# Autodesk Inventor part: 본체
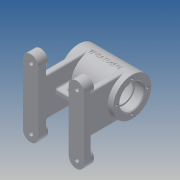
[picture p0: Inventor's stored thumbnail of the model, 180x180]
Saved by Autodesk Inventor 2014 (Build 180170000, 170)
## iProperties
Created: 2015-11
Part Number: 본체
Material: 일반
Document SubType Name: Modeling
Designer: Owner
Density: 1 g/cm^3
Appearance: 기본값
Author: Owner
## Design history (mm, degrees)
sketch "스케치1"
  geometry: L1 (0, 0)-(0, 25); L2 (0, 25)-(70, 25); L3 (70, 25)-(70, 0); L4 (70, 0)-(0, 0)
  constraints: 8 end point, 3 perpendicular, 2 point on line, 1 vertical
  dimensions: "d0" = 50 diameter of L2 L4; "d1" = 70 distance between parallel lines of L3 L1
revolve "회전1" sketch "스케치1" stored, may be unused: angle "d2" = 90 deg
sketch "스케치2"
  geometry: L1 (0, 25)-(70, 25) reference; L2 (35, 25)-(35, 28); L3 (35, 28)-(40, 28); L4 (40, 28)-(40, 25); L5 (35, 25)-(40, 25); 1 further point
  constraints: 8 end point, 2 perpendicular, 1 collinear, 1 midpoint, 1 parallel, 1 point on line
  dimensions: "d4" = 10 diameter of L4 L2; "d5" = 28 distance from line of point (0, 0) L3
revolve "회전2" sketch "스케치2" stored, may be unused: angle "d6" = 90 deg
node "작업 평면3"
sketch "스케치4"
  geometry: L1 (0, 0)-(-11.228, 0); L2 (0, -25)-(0, 25) reference; L3 (-5, -40)-(-5, 40); L4 (0, -25)-(70, -25) reference; L5 (35, -25)-(35, -18.194); L6 (15, -40)-(15, 40); A1 r 10 centre (5, -40) between (-5, -40) and (15, -40); A2 r 10 centre (5, 40) between (15, 40) and (-5, 40)
  constraints: 8 end point, 4 point on circle, 2 centre point, 2 perpendicular, 2 tangent, 1 midpoint, 1 parallel, 1 symmetric about line
  dimensions: "d13" = 20 diameter of A1; "d14" = 20 diameter of A2; "d15" = 80 distance of A2.centre A1.centre; "d16" = 40 distance between parallel lines of L5 L3
extrude "돌출2" join sketch "스케치4" distance "d17" = 10; taper "d18" = 0 deg
sketch "스케치5"
  geometry: L1 (15, -40)-(15, 40) reference; L2 (7, 25)-(7, -25); L3 (7, 25)-(15, 25); L4 (7, -25)-(15, -25); L5 (15, 25)-(15, -25); 2 further points
  constraints: 8 end point, 2 parallel, 2 point on line, 1 collinear, 1 horizontal alignment, 1 midpoint, 1 perpendicular
  dimensions: "d20" = 50 distance of L2.start L2.end; "d21" = 8 distance between parallel lines of L2 L1
extrude "돌출3" join sketch "스케치5" stored distance "d22" = 10; taper "d23" = 0 deg
node "작업 평면4"
sketch "스케치6"
  geometry: C1 r 10 at (0, 80); C2 r 10 at (0, 0); A1 r 10 centre (0, 0) between (-10, 0) and (10, 0) reference; A2 r 10 centre (0, 80) between (10, 80) and (-10, 80) reference; 1 further point
  constraints: 2 centre point, 2 coincident, 2 concentric
extrude "돌출4" join sketch "스케치6" distance "d24" = 3; taper "d25" = 0 deg
hole "구멍1" diameter "d28" = 6; stored, may be unused: countersink angle "d32" = 90 deg, drill point angle "d34" = 118 deg; dims "d26" = 10, "d27" = 10, "d29" = 6, "d30" = 12, "d31" = 4, "d33" = 8
sketch "스케치7"
  geometry: C1 r 10 at (5, 40); C2 r 10 at (5, -40); A1 r 10 centre (5, 40) between (15, 40) and (-5, 40) reference; A2 r 10 centre (5, -40) between (-5, -40) and (15, -40) reference; 1 further point
  constraints: 2 centre point, 2 coincident, 2 concentric
extrude "돌출5" join sketch "스케치7" distance "d38" = 3; taper "d39" = 0 deg
fillet "모깎기1" dims "d40" = 0.3
sketch "스케치8"
  geometry: L1 (0, 0)-(70, 0); L2 (0, 0)-(0, 16); L3 (0, -25)-(0, 25) reference; L4 (0, 16)-(12, 16); L5 (12, 16)-(12, 14); L6 (12, 14)-(14, 14); L7 (14, 14)-(14, 21); L8 (14, 21)-(56, 21); L9 (56, 21)-(56, 14); L10 (56, 14)-(58, 14); L11 (58, 14)-(58, 16); L12 (58, 16)-(70, 16); L13 (70, 16)-(70, 0); L14 (70, -25)-(70, 25) reference
  constraints: 24 end point, 7 parallel, 2 perpendicular, 1 collinear, 1 horizontal, 1 midpoint, 1 point on line
  dimensions: "d41" = 32 diameter of L4 L1; "d42" = 32 diameter of L12 L1; "d43" = 12 distance between parallel lines of L2 L5; "d44" = 12 distance between parallel lines of L13 L11; "d46" = 2 distance between parallel lines of L5 L7; "d47" = 2 distance between parallel lines of L11 L9; "d48" = 28 diameter of L6 L1; "d49" = 28 diameter of L10 L1; "d50" = 42 diameter of L8 L1
revolve "회전3" sketch "스케치8" stored, may be unused: angle "d51" = 90 deg
fillet "모깎기2" dims "d52" = 3
fillet "모깎기3" dims "d53" = 0.3
sketch "스케치9"
  geometry: C1 r 16 at (0, 0) reference; C2 r 25 at (0, 0) reference; C3 r 21 at (0, 0) reference; A1 r 20 centre (0, 0) between (0, 20) and (20, 0); 2 further points
  constraints: 4 point on circle, 2 horizontal alignment, 2 vertical alignment, 1 centre point, 1 coincident
  dimensions: "d54" = 40 diameter of A1
hole "구멍2" sketch "스케치9" at (0, 20), (20, 0), (0, -20), (-20, 0) diameter "d55" = 3.242; stored, may be unused: countersink angle "d59" = 90 deg, drill point angle "d61" = 118 deg; dims "d56" = 8, "d57" = 12, "d58" = 4, "d60" = 10
sketch "스케치10"
  geometry: L1 (0, 0)-(0, -18.621); L2 (-24.249, -14)-(-21.249, -19.196); L3 (-21.249, -19.196)-(-18.018, -17.331); L4 (-24.249, -14)-(-21.651, -12.5); L5 (0, 0)-(-9.403, 0); L6 (-21.651, -12.5)-(0, 0); A1 r 25 centre (0, 0) between (0, 25) and (0, -25) reference
  constraints: 12 end point, 2 perpendicular, 2 point on circle, 1 collinear, 1 parallel, 1 vertical
  dimensions: "d65" = 12 diameter of L3 L4; "d68" = 30 deg angle of L5 L6; "d73" = 28 distance from line of L5.start L2
revolve "회전4" sketch "스케치10" stored, may be unused: angle "d74" = 90 deg
hole "구멍3" diameter "d77" = 5.188; stored, may be unused: countersink angle "d81" = 90 deg, drill point angle "d83" = 118 deg; dims "d75" = 10, "d76" = 10, "d78" = 20, "d79" = 12, "d80" = 4, "d82" = 10
hole "구멍4" diameter "d86" = 5.188; stored, may be unused: countersink angle "d90" = 90 deg, drill point angle "d92" = 118 deg; dims "d84" = 10, "d85" = 10, "d87" = 20, "d88" = 12, "d89" = 4, "d91" = 10
sketch "스케치11"
  geometry: L1 (15, -58)-(15, 0) reference; L2 (15, -45)-(55, -45); L3 (75, -68)-(55, -68) reference; L4 (0, -25)-(70, -25) reference; L5 (15, -45)-(15, -25); L6 (15, -25)-(55, -25); L7 (55, -58)-(55, 0) reference; L8 (55, -25)-(55, -45); 1 further point
  constraints: 8 end point, 5 point on line, 1 collinear, 1 perpendicular
  dimensions: "d94" = 20 distance between parallel lines of L2 L4
extrude "돌출6" join sketch "스케치11" stored distance "d95" = 8; taper "d96" = 0 deg
sketch "스케치12"
  geometry: L1 (55, -25)-(15, -25) reference; L2 (-5, -68)-(15, -68) reference; L3 (27, -31.5)-(43, -31.5); L4 (27, -38.5)-(43, -38.5); A1 r 3.5 centre (27, -35) between (27, -31.5) and (27, -38.5); A2 r 3.5 centre (43, -35) between (43, -38.5) and (43, -31.5); 3 further points
  constraints: 4 end point, 4 point on circle, 2 centre point, 2 midpoint, 2 parallel, 2 tangent, 1 horizontal alignment, 1 vertical alignment
  dimensions: "d97" = 33 distance from line of L2 A1.centre; "d98" = 7 diameter of A1; "d99" = 7 diameter of A2; "d100" = 23 dimension on A2 A1
extrude "돌출7" cut sketch "스케치12" distance "d101" = 10; taper "d102" = 0 deg
fillet "모깎기4" dims "d103" = 2
fillet "모깎기5" dims "d104" = 2
fillet "모깎기6" dims "d105" = 2
fillet "모깎기7" dims "d106" = 2
node "작업 평면6"
sketch "스케치13"
  geometry: L1 (-35, 25)-(35, 25) reference; L2 (-35, -25)-(-35, 25) reference; L3 (-20.739, 3.002)-(20.739, 3.002); L4 (20.739, 3.002)-(20.739, -3.002); L5 (20.739, -3.002)-(-20.739, -3.002); L6 (-20.739, -3.002)-(-20.739, 3.002); L7 (-20.739, 0)-(20.739, 0); L8 (0, 3.002)-(0, -3.002); 1 further point
  constraints: 4 end point, 4 midpoint, 2 other
  dimensions: "d107" = 35 distance between parallel lines of L8 L2; "d108" = 25 distance between parallel lines of L1 L7
feature "엠보싱1" sketch "스케치13" dims "d109" = 0.5, "d110" = 0
fillet "모깎기8" dims "d111" = 2
chamfer "모따기1" distance "d112" = 1; stored, may be unused: second distance "d113" = 2, angle "d114" = 45 deg
node "솔리드1"
mirror "대칭1"
pattern_linear "직사각형 패턴1" dims "d37" = 80
mirror "대칭2"
mirror "대칭3"
other parameters: "d12" = -68
